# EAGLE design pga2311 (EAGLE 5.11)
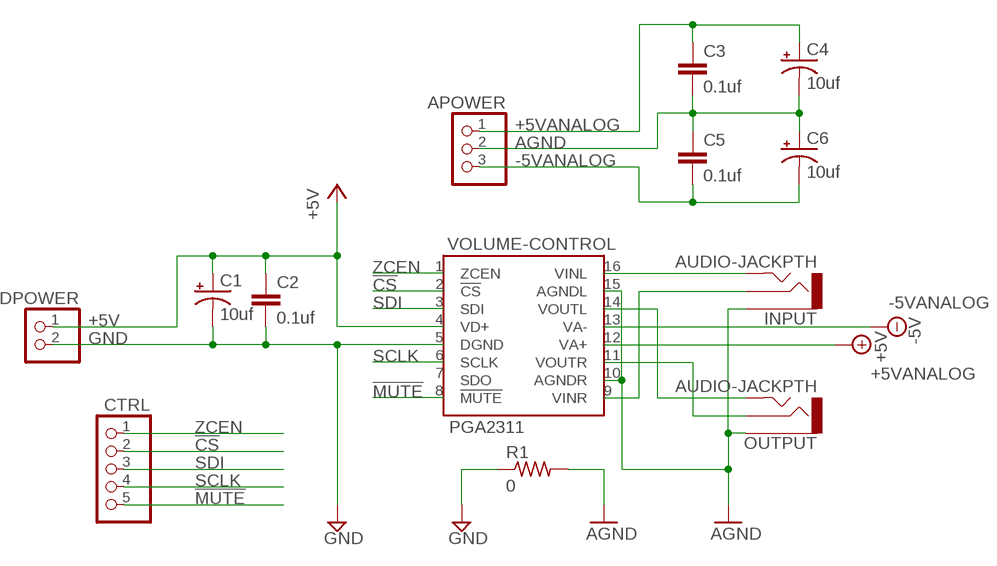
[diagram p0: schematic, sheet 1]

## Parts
APOWER  PINHD-1X3  [1X03]
C1  10uf  CPOL-USE2-5  [E2-5]
C2  0.1uf  C-EUC0805  [C0805]
C3  0.1uf  C-EUC0805  [C0805]
C4  10uf  CPOL-USE2-5  [E2-5]
C5  0.1uf  C-EUC0805  [C0805]
C6  10uf  CPOL-USE2-5  [E2-5]
CTRL  PINHD-1X5  [1X05]
DPOWER  PINHD-1X2  [1X02]
INPUT  AUDIO-JACKPTH  [AUDIO-JACK]
OUTPUT  AUDIO-JACKPTH  [AUDIO-JACK]
R1  0  R-US_R1206  [R1206]
VOLUME-CONTROL  PGA2311  [DIL16-3]

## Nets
!CS: CTRL.2 VOLUME-CONTROL.2(!CS)
!MUTE: CTRL.5 VOLUME-CONTROL.8(!MUTE)
+5V: C1.+ C2.1 DPOWER.1 VOLUME-CONTROL.4(VD+)
+5VANALOG: APOWER.1 C3.1 C4.+ VOLUME-CONTROL.12(VA+) ; supply symbol labelled +5V
-5VANALOG: APOWER.3 C5.2 C6.- VOLUME-CONTROL.13(VA-) ; supply symbol labelled -5V
AGND: APOWER.2 C3.2 C4.- C5.1 C6.+ INPUT.1 OUTPUT.1 R1.2 VOLUME-CONTROL.10(AGNDR) VOLUME-CONTROL.15(AGNDL)
GND: C1.- C2.2 DPOWER.2 R1.1 VOLUME-CONTROL.5(DGND)
N$2: OUTPUT.2 VOLUME-CONTROL.11(VOUTR)
N$3: OUTPUT.5 VOLUME-CONTROL.14(VOUTL)
N$4: INPUT.5 VOLUME-CONTROL.16(VINL)
N$6: INPUT.2 VOLUME-CONTROL.9(VINR)
SCLK: CTRL.4 VOLUME-CONTROL.6(SCLK)
SDI: CTRL.3 VOLUME-CONTROL.3(SDI)
ZCEN: CTRL.1 VOLUME-CONTROL.1(ZCEN)
Unconnected: VOLUME-CONTROL.7(SDO)

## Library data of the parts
APOWER = pinhead:PINHD-1X3: PIN HEADER
C1 C4 C6 = rcl:CPOL-US: POLARIZED CAPACITOR, American symbol
C2 C3 C5 = rcl:C-EU: CAPACITOR, European symbol
CTRL = pinhead:PINHD-1X5: PIN HEADER
DPOWER = pinhead:PINHD-1X2: PIN HEADER
INPUT OUTPUT = SparkFun:AUDIO-JACK: 3.5mm Audio Jack Simple 3.5mm common PCB mount audio jack. SKU: PRT-08032
R1 = resistor:R-US_: RESISTOR, American symbol
VOLUME-CONTROL = trl:PGA2311

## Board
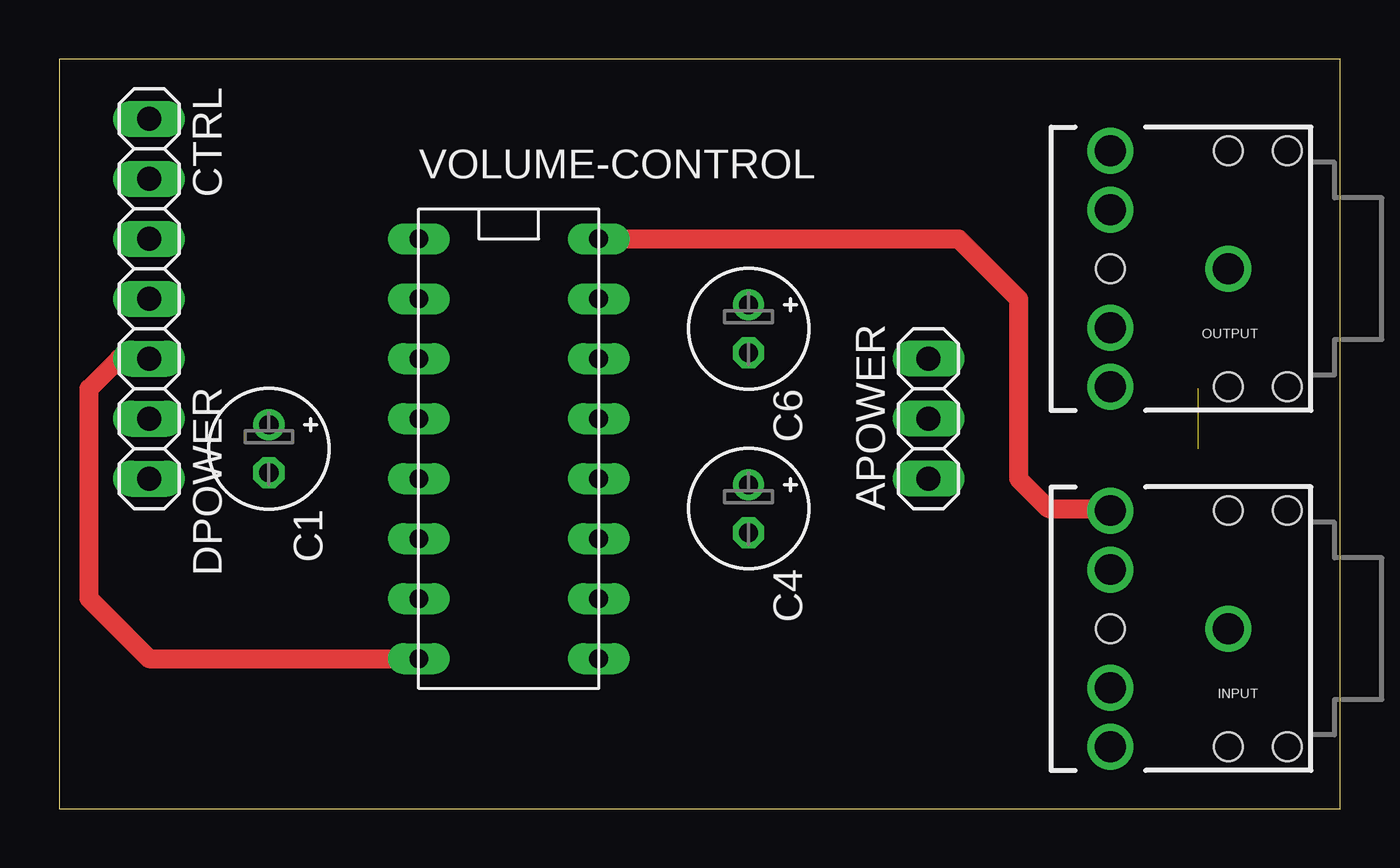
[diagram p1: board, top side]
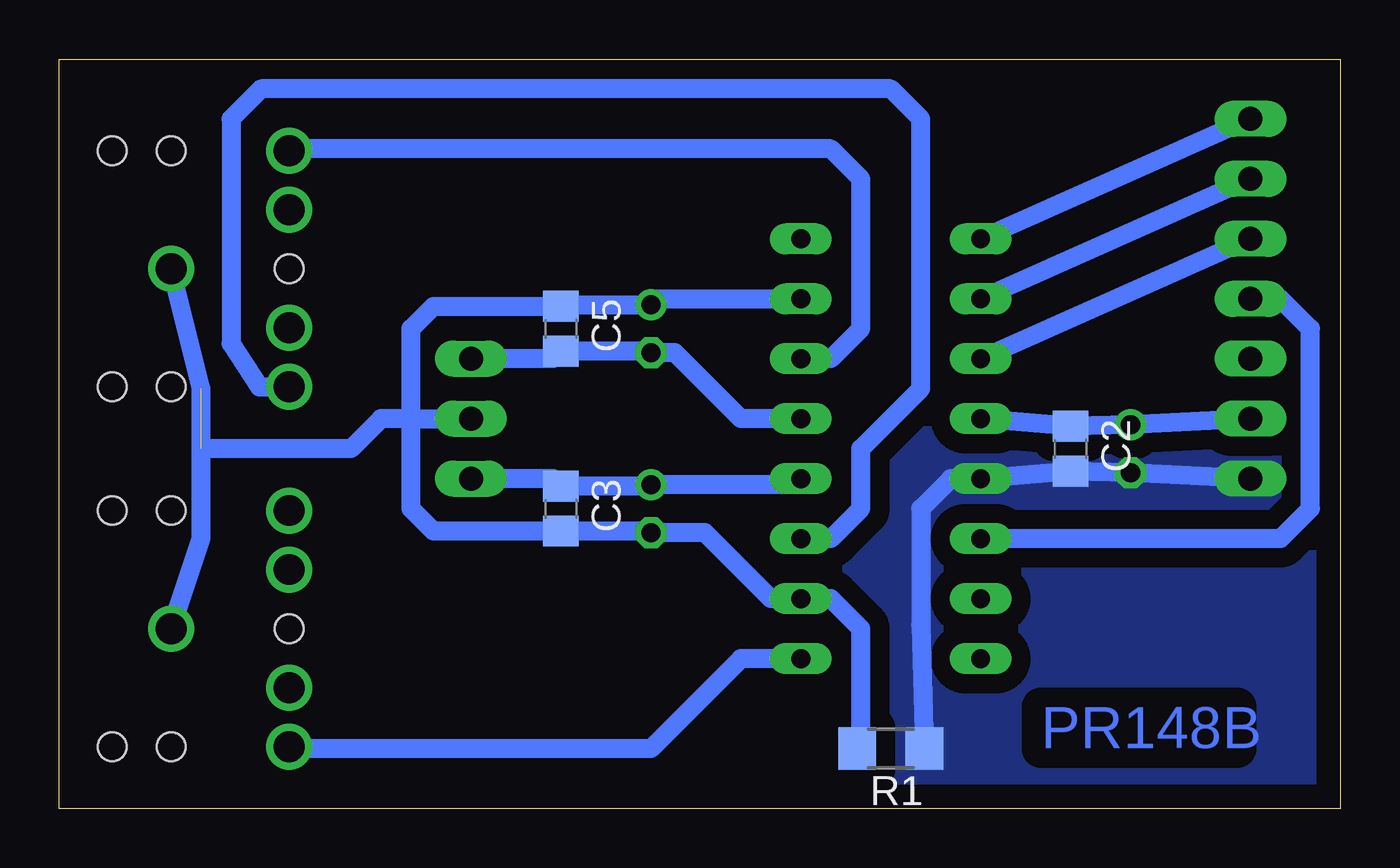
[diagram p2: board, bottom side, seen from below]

Size 54.28 x 31.74 mm. Coordinates in mm from the lower left corner, seen from the top.
Outline: 0,0 54.28,0 54.28,31.74 0,31.74 0,0
Copper layers (1*16): Top 0.035mm / dielectric 1.5mm / Bottom 0.035mm
Design rules "default": minimum track width 10mil, minimum drill 24mil, track to track 8mil, track to pad 8mil, pad to pad 8mil, via to via 8mil, smd to smd 8mil, copper to edge 40mil, drill to drill 8mil, minimum pad ring 10mil, minimum via ring 8mil, stop-mask expansion 4mil, vias tented up to drill 0mil, thermal gap 10mil

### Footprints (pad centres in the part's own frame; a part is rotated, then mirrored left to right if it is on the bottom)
1X03 = drill 1.016 long: 1 -2.54,0; 2 0,0; 3 2.54,0
E2-5 = drill 0.813 pad 1.27 round: + -1.016,0 | drill 0.813 pad 1.27 octagon: - 1.016,0
C0805 = smd 1.3 x 1.5: 1 -0.95,0; 2 0.95,0
1X05 = drill 1.016 long: 1 -5.08,0; 2 -2.54,0; 3 0,0; 4 2.54,0; 5 5.08,0
1X02 = drill 1.016 long: 1 -1.27,0; 2 1.27,0
AUDIO-JACK = drill 1.3 round: 1 0,0; 2 5,5; 3 5,2.5; 4 5,-2.5; 5 5,-5 | hole 1.2: 0,5; -2.5,5; -2.5,-5; 0,-5; 5,0
R1206 = smd 1.6 x 1.803: 1 -1.422,0; 2 1.422,0
DIL16-3 = drill 0.8 long: 1 -3.81,8.89; 2 -3.81,6.35; 3 -3.81,3.81; 4 -3.81,1.27; 5 -3.81,-1.27; 6 -3.81,-3.81; 7 -3.81,-6.35; 8 -3.81,-8.89; 9 3.81,-8.89; 10 3.81,-6.35; 11 3.81,-3.81; 12 3.81,-1.27; 13 3.81,1.27; 14 3.81,3.81; 15 3.81,6.35; 16 3.81,8.89

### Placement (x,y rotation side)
APOWER  36.83,16.51 90 top
C1  8.89,15.24 270 top
C2  11.43,15.24 270 bottom
C3  33.02,12.7 270 bottom
C4  29.21,12.7 270 top
C5  33.02,20.32 270 bottom
C6  29.21,20.32 270 top
CTRL  3.81,24.13 270 top
DPOWER  3.81,15.24 270 top
INPUT  49.53,7.62 180 top
OUTPUT  49.53,22.86 180 top
R1  19.05,2.54 180 bottom
VOLUME-CONTROL  19.05,15.24 0 top

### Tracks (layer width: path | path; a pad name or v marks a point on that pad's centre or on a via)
!CS
  Bottom 0.813: CTRL.2 VOLUME-CONTROL.2
!MUTE
  Top 0.813: VOLUME-CONTROL.8 3.81,6.35 1.27,8.89 1.27,17.78 2.54,19.05 CTRL.5
+5V
  Bottom 0.813: VOLUME-CONTROL.4 C2.1 C1.+ DPOWER.1
+5VANALOG
  Bottom 0.813: APOWER.1 33.34,13.97 C3.1 29.28,13.65 C4.+ 23.11,13.72 VOLUME-CONTROL.12
-5VANALOG
  Bottom 0.813: APOWER.3 33.34,19.05 C5.2 29.28,19.37 C6.- 28.19,19.3 25.4,16.51 VOLUME-CONTROL.13
AGND  (1 unrouted)
  Bottom 0.813: INPUT.1 48.26,11.43 48.26,17.78 OUTPUT.1 | 39.37,16.51 APOWER.2 | 39.37,16.51 40.64,16.51 41.91,15.24 48.26,15.24 | VOLUME-CONTROL.15 28.96,21.59 C6.+ 32.95,21.34 C5.1 38.42,21.27 39.37,20.32 39.37,16.51 | 39.37,16.51 39.37,12.7 38.42,11.75 C3.2 29.28,11.75 C4.- 26.92,11.68 24.13,8.89 VOLUME-CONTROL.10 21.59,8.89 20.32,7.62 20.32,2.69 R1.2
GND
  Bottom 0.813: DPOWER.2 C1.- C2.2 VOLUME-CONTROL.5 16.51,13.97 17.78,12.7 17.78,7.77 R1.1
  pour Bottom (isolate 0.813, no thermals): 0,31.75 54.61,31.75 54.61,0 0,0
N$2
  Bottom 0.813: VOLUME-CONTROL.11 21.59,11.43 20.32,12.7 20.32,15.24 17.78,17.78 17.78,29.21 19.05,30.48 45.72,30.48 46.99,29.21 46.99,19.68 45.8,17.86 OUTPUT.2
N$3
  Bottom 0.813: VOLUME-CONTROL.14 21.59,19.05 20.32,20.32 20.32,26.67 21.59,27.94 44.45,27.94 OUTPUT.5
N$4
  Top 0.813: VOLUME-CONTROL.16 38.1,24.13 40.64,21.59 40.64,13.97 41.91,12.7 44.45,12.7 INPUT.5
N$6
  Bottom 0.813: VOLUME-CONTROL.9 25.4,6.35 29.21,2.54 44.45,2.54 INPUT.2
SCLK
  Bottom 0.813: VOLUME-CONTROL.6 2.54,11.43 1.27,12.7 1.27,20.32 2.54,21.59 CTRL.4
SDI
  Bottom 0.813: CTRL.3 VOLUME-CONTROL.3
ZCEN
  Bottom 0.813: CTRL.1 VOLUME-CONTROL.1

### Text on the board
Bottom: PR148B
